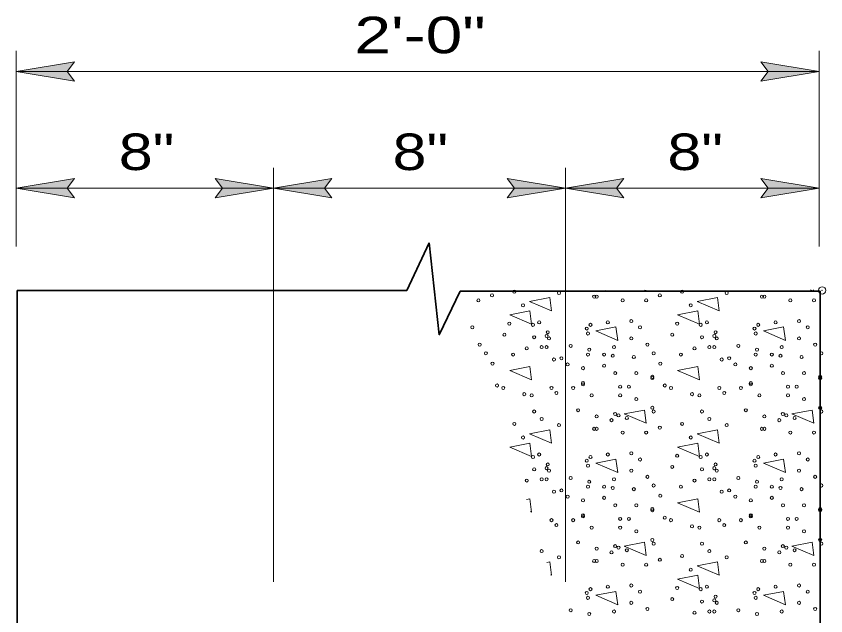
# Model space of a CAD drawing. Extents: x -43.06 to -36.2, y -1.41 to 7.25.
# Drawn here: x -41.523 to -40.192, y 6.232 to 7.218 of the extents above; entities that cross this region are included whole.
import ezdxf
from ezdxf.enums import TextEntityAlignment as Align

# ---------------------------------------------------------------- set-up
doc = ezdxf.new("R2010")
doc.units = 0
doc.header["$LTSCALE"] = 0.024
doc.header["$PDMODE"] = 32
doc.header["$PDSIZE"] = 0.012
for name, color, linetype, lineweight in [('1', 7, 'Continuous', 35), ('10', 7, 'Continuous', 13), ('12', 7, 'Continuous', 53), ('6', 7, 'Continuous', 13)]:
    doc.layers.add(name, color=color, linetype=linetype, lineweight=lineweight)

msp = doc.modelspace()

# ---------------------------------------------------------------- hatches: boundary and pattern name
at = {"layer": '10'}
for points in [[(-41.42708, 7.11083), (-41.43908, 7.12683), (-41.42708, 7.14283), (-41.52308, 7.12683)], [(-40.20292, 7.12683), (-40.29892, 7.11083), (-40.28692, 7.12683), (-40.29892, 7.14283)], [(-41.52308, 6.93483), (-41.42708, 6.91883), (-41.43908, 6.93483), (-41.42708, 6.95083)], [(-41.09992, 6.93483), (-41.19592, 6.91883), (-41.18392, 6.93483), (-41.19592, 6.95083)], [(-41.09992, 6.93483), (-41.00392, 6.91883), (-41.01592, 6.93483), (-41.00392, 6.95083)], [(-40.61992, 6.93483), (-40.71592, 6.95083), (-40.70392, 6.93483), (-40.71592, 6.91883)], [(-40.61992, 6.93483), (-40.52392, 6.91883), (-40.53592, 6.93483), (-40.52392, 6.95083)], [(-40.20292, 6.93483), (-40.29892, 6.91883), (-40.28692, 6.93483), (-40.29892, 6.95083)]]:
    msp.add_hatch(color=256, dxfattribs=at).paths.add_polyline_path(points)

# ---------------------------------------------------------------- linework, layer by layer
at = {"layer": '1'}
for p, q in [((-41.52158, 6.09917), (-41.52158, 6.76683)), ((-40.20142, 6.09917), (-40.20142, 6.76583))]:
    msp.add_line(p, q, dxfattribs=at)
at = {"layer": '10'}
for p, q in [((-41.52308, 6.83883), (-41.52308, 7.1605)), ((-40.20292, 6.83883), (-40.20292, 7.1605)), ((-41.52308, 7.12683), (-40.20292, 7.12683)), ((-41.09992, 6.28767), (-41.09992, 6.9685)), ((-40.61992, 6.28767), (-40.61992, 6.9685))]:
    msp.add_line(p, q, dxfattribs=at)
at = {"layer": '10', "lineweight": 35}
for p, q in [((-40.84425, 6.84483), (-40.88058, 6.76683)), ((-40.88058, 6.76683), (-41.52158, 6.76683)), ((-40.79325, 6.76583), (-40.20142, 6.76583))]:
    msp.add_line(p, q, dxfattribs=at)
at = {"layer": '10'}
for points in [[(-41.42708, 7.11083), (-41.43908, 7.12683), (-41.42708, 7.14283), (-41.52308, 7.12683)], [(-40.20292, 7.12683), (-40.29892, 7.11083), (-40.28692, 7.12683), (-40.29892, 7.14283)], [(-41.52308, 6.93483), (-41.42708, 6.91883), (-41.43908, 6.93483), (-41.42708, 6.95083)], [(-41.09992, 6.93483), (-41.19592, 6.91883), (-41.18392, 6.93483), (-41.19592, 6.95083)], [(-41.09992, 6.93483), (-41.00392, 6.91883), (-41.01592, 6.93483), (-41.00392, 6.95083)], [(-40.61992, 6.93483), (-40.71592, 6.95083), (-40.70392, 6.93483), (-40.71592, 6.91883)], [(-40.61992, 6.93483), (-40.52392, 6.91883), (-40.53592, 6.93483), (-40.52392, 6.95083)], [(-40.20292, 6.93483), (-40.29892, 6.91883), (-40.28692, 6.93483), (-40.29892, 6.95083)]]:
    msp.add_lwpolyline(points, close=True, dxfattribs=at)
msp.add_lwpolyline([(-41.52308, 6.93483), (-41.09992, 6.93483), (-40.61992, 6.93483), (-40.20292, 6.93483)], dxfattribs=at)
at = {"layer": '10', "lineweight": 35}
msp.add_lwpolyline([(-40.84425, 6.84483), (-40.82742, 6.69383), (-40.79325, 6.76583)], dxfattribs=at)
at = {"layer": '6'}
for points in [[(-40.76308, 6.76583), (-40.76308, 6.76567), (-40.76358, 6.76583)], [(-40.55108, 6.76683), (-40.55092, 6.7655), (-40.55375, 6.76683)], [(-40.48758, 6.767), (-40.48742, 6.76567), (-40.49025, 6.767)], [(-40.21192, 6.768), (-40.21158, 6.76567), (-40.21708, 6.768)], [(-40.71142, 6.50933), (-40.67842, 6.51583), (-40.67558, 6.49383), (-40.71142, 6.50917)], [(-40.68392, 6.423), (-40.67842, 6.42417), (-40.67558, 6.40233), (-40.67758, 6.40317)], [(-40.65075, 6.31933), (-40.64592, 6.32033), (-40.64308, 6.29833), (-40.64442, 6.299)]]:
    msp.add_lwpolyline(points, dxfattribs=at)
for points in [[(-40.67892, 6.7485), (-40.64592, 6.755), (-40.64308, 6.73317)], [(-40.40325, 6.7485), (-40.37008, 6.755), (-40.36725, 6.73317)], [(-40.71158, 6.72667), (-40.67842, 6.73317), (-40.67558, 6.71117)], [(-40.43575, 6.72667), (-40.40258, 6.73317), (-40.39975, 6.71117)], [(-40.57008, 6.70017), (-40.53708, 6.70667), (-40.53408, 6.68467)], [(-40.29425, 6.70017), (-40.26125, 6.70667), (-40.25842, 6.68467)], [(-40.71158, 6.635), (-40.67842, 6.6415), (-40.67558, 6.61967)], [(-40.43575, 6.635), (-40.40258, 6.6415), (-40.39975, 6.61967)], [(-40.52325, 6.56383), (-40.49025, 6.57017), (-40.48742, 6.54833)], [(-40.24758, 6.56383), (-40.21442, 6.57017), (-40.21158, 6.54833)], [(-40.67892, 6.53117), (-40.64592, 6.53767), (-40.64308, 6.51583)], [(-40.40325, 6.53117), (-40.37008, 6.53767), (-40.36725, 6.51583)], [(-40.43575, 6.50933), (-40.40258, 6.51583), (-40.39975, 6.49383)], [(-40.57008, 6.48283), (-40.53708, 6.48933), (-40.53408, 6.46733)], [(-40.29425, 6.48283), (-40.26125, 6.48933), (-40.25842, 6.46733)], [(-40.43575, 6.41767), (-40.40258, 6.42417), (-40.39975, 6.40233)], [(-40.52325, 6.34633), (-40.49025, 6.35283), (-40.48742, 6.331)], [(-40.24758, 6.34633), (-40.21442, 6.35283), (-40.21158, 6.331)], [(-40.40325, 6.31383), (-40.37008, 6.32033), (-40.36725, 6.29833)], [(-40.43575, 6.292), (-40.40258, 6.29833), (-40.39975, 6.2765)], [(-40.57008, 6.2655), (-40.53708, 6.272), (-40.53408, 6.25)], [(-40.29425, 6.2655), (-40.26125, 6.272), (-40.25842, 6.25)]]:
    msp.add_lwpolyline(points, close=True, dxfattribs=at)
for centre in [(-40.70399, 6.76472), (-40.6307, 6.76268), (-40.42818, 6.76472), (-40.35489, 6.76268), (-40.76304, 6.75048), (-40.74063, 6.7586), (-40.57273, 6.75656), (-40.56869, 6.75656), (-40.52592, 6.75048), (-40.48723, 6.75048), (-40.46483, 6.7586), (-40.29692, 6.75656), (-40.29288, 6.75656), (-40.25011, 6.75048), (-40.21143, 6.75048), (-40.68974, 6.74232), (-40.41394, 6.74232), (-40.71215, 6.71227), (-40.67346, 6.71023), (-40.66326, 6.71431), (-40.57885, 6.71023), (-40.55036, 6.71431), (-40.51168, 6.71635), (-40.43634, 6.71227), (-40.39766, 6.71023), (-40.38746, 6.71431), (-40.30304, 6.71023), (-40.27456, 6.71431), (-40.23587, 6.71635), (-40.7732, 6.70615), (-40.72027, 6.69395), (-40.64902, 6.69803), (-40.58497, 6.70411), (-40.58293, 6.69599), (-40.49739, 6.70615), (-40.44447, 6.69395), (-40.37321, 6.69803), (-40.30916, 6.70411), (-40.30712, 6.69599), (-40.22159, 6.70615), (-40.67142, 6.68987), (-40.65106, 6.69191), (-40.64698, 6.68783), (-40.51168, 6.68783), (-40.39562, 6.68987), (-40.37525, 6.69191), (-40.37117, 6.68783), (-40.23587, 6.68783), (-40.761, 6.67767), (-40.68362, 6.67155), (-40.65922, 6.67359), (-40.65106, 6.67359), (-40.61141, 6.67563), (-40.58089, 6.66951), (-40.54016, 6.67359), (-40.48519, 6.67767), (-40.40782, 6.67155), (-40.38342, 6.67359), (-40.37525, 6.67359), (-40.33561, 6.67563), (-40.30508, 6.66951), (-40.26436, 6.67359), (-40.20939, 6.67767), (-40.75083, 6.66342), (-40.70603, 6.66138), (-40.62661, 6.65526), (-40.58293, 6.66138), (-40.55644, 6.66138), (-40.5422, 6.65934), (-40.5076, 6.6573), (-40.47503, 6.66342), (-40.43022, 6.66138), (-40.35081, 6.65526), (-40.30712, 6.66138), (-40.28064, 6.66138), (-40.2664, 6.65934), (-40.23179, 6.6573), (-40.19923, 6.66342), (-40.73991, 6.6465), (-40.63886, 6.65322), (-40.61645, 6.6451), (-40.55644, 6.64306), (-40.46411, 6.6465), (-40.36305, 6.65322), (-40.34065, 6.6451), (-40.28064, 6.64306), (-40.59105, 6.63898), (-40.53812, 6.63082), (-40.50351, 6.63082), (-40.31524, 6.63898), (-40.26232, 6.63082), (-40.22771, 6.63082), (-40.59105, 6.61454), (-40.47703, 6.62474), (-40.47703, 6.6227), (-40.31524, 6.61454), (-40.20123, 6.62474), (-40.20123, 6.6227), (-40.73251, 6.61046), (-40.72231, 6.60642), (-40.6429, 6.60642), (-40.60733, 6.60642), (-40.59105, 6.6125), (-40.53, 6.60846), (-40.51572, 6.60846), (-40.45671, 6.61046), (-40.44651, 6.60642), (-40.36709, 6.60642), (-40.33153, 6.60642), (-40.31524, 6.6125), (-40.2542, 6.60846), (-40.23991, 6.60846), (-40.6877, 6.59621), (-40.6755, 6.59417), (-40.63478, 6.59825), (-40.57681, 6.59417), (-40.53, 6.59417), (-40.50351, 6.58809), (-40.4119, 6.59621), (-40.3997, 6.59417), (-40.35897, 6.59825), (-40.301, 6.59417), (-40.2542, 6.59417), (-40.22771, 6.58809), (-40.47703, 6.57381), (-40.20123, 6.57381), (-40.67142, 6.56773), (-40.59921, 6.56977), (-40.53836, 6.56373), (-40.53272, 6.56129), (-40.47503, 6.56773), (-40.39562, 6.56773), (-40.32341, 6.56977), (-40.26256, 6.56373), (-40.25692, 6.56129), (-40.19923, 6.56773), (-40.70399, 6.54737), (-40.65922, 6.55549), (-40.56869, 6.55957), (-40.54424, 6.55349), (-40.51908, 6.55693), (-40.42818, 6.54737), (-40.38342, 6.55549), (-40.29288, 6.55957), (-40.26844, 6.55349), (-40.24327, 6.55693), (-40.6307, 6.54533), (-40.57273, 6.5392), (-40.56869, 6.5392), (-40.46483, 6.54125), (-40.35489, 6.54533), (-40.29692, 6.5392), (-40.29288, 6.5392), (-40.68974, 6.52496), (-40.52592, 6.53312), (-40.48723, 6.53312), (-40.41394, 6.52496), (-40.25011, 6.53312), (-40.21143, 6.53312), (-40.66326, 6.49696), (-40.55036, 6.49696), (-40.51168, 6.499), (-40.43634, 6.49492), (-40.38746, 6.49696), (-40.27456, 6.49696), (-40.23587, 6.499), (-40.67346, 6.49288), (-40.64902, 6.48068), (-40.58497, 6.48676), (-40.57885, 6.49288), (-40.49739, 6.4888), (-40.39766, 6.49288), (-40.37321, 6.48068), (-40.30916, 6.48676), (-40.30304, 6.49288), (-40.22159, 6.4888), (-40.67142, 6.47251), (-40.65106, 6.47455), (-40.64698, 6.47047), (-40.58293, 6.47864), (-40.51168, 6.47047), (-40.44447, 6.47659), (-40.39562, 6.47251), (-40.37525, 6.47455), (-40.37117, 6.47047), (-40.30712, 6.47864), (-40.23587, 6.47047), (-40.68362, 6.45419), (-40.65922, 6.45623), (-40.65106, 6.45623), (-40.61141, 6.45827), (-40.54016, 6.45623), (-40.48519, 6.46031), (-40.40782, 6.45419), (-40.38342, 6.45623), (-40.37525, 6.45623), (-40.33561, 6.45827), (-40.26436, 6.45623), (-40.20939, 6.46031), (-40.58293, 6.44403), (-40.58089, 6.45215), (-40.55644, 6.44403), (-40.5422, 6.44199), (-40.47503, 6.44607), (-40.43022, 6.44403), (-40.30712, 6.44403), (-40.30508, 6.45215), (-40.28064, 6.44403), (-40.2664, 6.44199), (-40.19923, 6.44607), (-40.63886, 6.43587), (-40.62661, 6.43791), (-40.61645, 6.42775), (-40.5076, 6.43995), (-40.46411, 6.42915), (-40.36305, 6.43587), (-40.35081, 6.43791), (-40.34065, 6.42775), (-40.23179, 6.43995), (-40.59105, 6.42163), (-40.55644, 6.42571), (-40.31524, 6.42163), (-40.28064, 6.42571), (-40.53812, 6.41346), (-40.50351, 6.41346), (-40.47703, 6.40738), (-40.47703, 6.40534), (-40.26232, 6.41346), (-40.22771, 6.41346), (-40.20123, 6.40738), (-40.20123, 6.40534), (-40.6429, 6.38906), (-40.60733, 6.38906), (-40.59105, 6.39718), (-40.59105, 6.39514), (-40.53, 6.3911), (-40.51572, 6.3911), (-40.45671, 6.3931), (-40.44651, 6.38906), (-40.36709, 6.38906), (-40.33153, 6.38906), (-40.31524, 6.39718), (-40.31524, 6.39514), (-40.2542, 6.3911), (-40.23991, 6.3911), (-40.63478, 6.3809), (-40.57681, 6.37682), (-40.53, 6.37682), (-40.4119, 6.37886), (-40.3997, 6.37682), (-40.35897, 6.3809), (-40.301, 6.37682), (-40.2542, 6.37682), (-40.50351, 6.37074), (-40.22771, 6.37074), (-40.59921, 6.35242), (-40.47703, 6.35646), (-40.47503, 6.35037), (-40.39562, 6.35037), (-40.32341, 6.35242), (-40.20123, 6.35646), (-40.19923, 6.35037), (-40.65922, 6.33813), (-40.56869, 6.34221), (-40.54424, 6.33613), (-40.53836, 6.34637), (-40.53272, 6.34393), (-40.51908, 6.33957), (-40.38342, 6.33813), (-40.29288, 6.34221), (-40.26844, 6.33613), (-40.26256, 6.34637), (-40.25692, 6.34393), (-40.24327, 6.33957), (-40.6307, 6.32797), (-40.57273, 6.32185), (-40.56869, 6.32185), (-40.46483, 6.32389), (-40.42818, 6.33001), (-40.35489, 6.32797), (-40.29692, 6.32185), (-40.29288, 6.32185), (-40.52592, 6.31577), (-40.48723, 6.31577), (-40.41394, 6.30761), (-40.25011, 6.31577), (-40.21143, 6.31577), (-40.51168, 6.28164), (-40.23587, 6.28164), (-40.58497, 6.2694), (-40.57885, 6.27552), (-40.55036, 6.2796), (-40.49739, 6.27144), (-40.43634, 6.27756), (-40.39766, 6.27552), (-40.38746, 6.2796), (-40.30916, 6.2694), (-40.30304, 6.27552), (-40.27456, 6.2796), (-40.22159, 6.27144), (-40.58293, 6.26128), (-40.44447, 6.25924), (-40.39562, 6.25516), (-40.37525, 6.2572), (-40.37321, 6.26332), (-40.30712, 6.26128), (-40.61141, 6.24092), (-40.51168, 6.25312), (-40.48519, 6.24296), (-40.37117, 6.25312), (-40.33561, 6.24092), (-40.23587, 6.25312), (-40.20939, 6.24296), (-40.58089, 6.2348), (-40.54016, 6.23888), (-40.40782, 6.23684), (-40.38342, 6.23888), (-40.37525, 6.23888), (-40.30508, 6.2348), (-40.26436, 6.23888)]:
    msp.add_circle(centre, 0.00252, dxfattribs=at)
msp.add_point((-40.19792, 6.76683), dxfattribs=at)

# ---------------------------------------------------------------- texts
at = {"layer": '12'}
for s, width, p in [('2\'-0"', 1.35, (-40.85908, 7.15683)), ('8"', 1.25, (-41.30875, 6.96475)), ('8"', 1.25, (-40.85858, 6.96475)), ('8"', 1.25, (-40.40667, 6.96475))]:
    msp.add_text(s, height=0.06001, dxfattribs=dict(at, width=width)).set_placement(p, align=Align.CENTER)

doc.saveas('drawing.dxf')
